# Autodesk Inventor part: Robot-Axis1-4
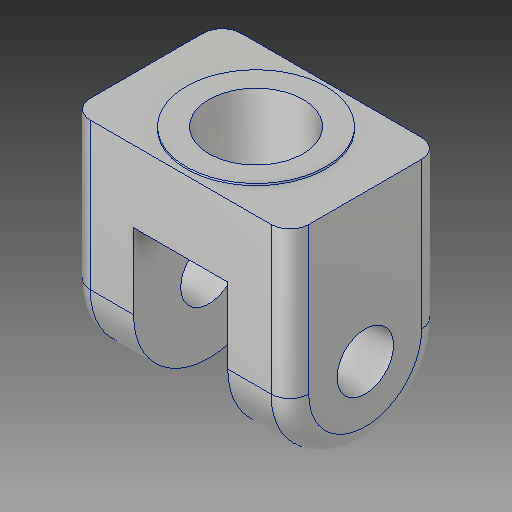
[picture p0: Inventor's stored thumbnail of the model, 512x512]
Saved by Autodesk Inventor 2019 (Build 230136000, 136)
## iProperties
Created: 2018-07
Part Number: Robot-Axis1-4
Material: Aluminum 6061
Description: 123456
Document SubType Name: Modeling
Designer: Power User
Mass: 1617.3 g
Surface Area: 678.793 cm^2
Volume: 599 cm^3
Density: 2.7 g/cm^3
Appearance: Aluminum - Flat
Title: GEAR
Author: Power User
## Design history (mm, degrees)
sketch "Sketch6" dims "d45" = 80
  geometry: L1 (0, 40)-(78, 40); L2 (78, 40)-(78, -40); L3 (78, -40)-(0, -40); L4 (0, -40)-(0, 40); 3 further points
  constraints: 8 end point, 3 horizontal, 2 parallel, 1 coincident, 1 midpoint, 1 perpendicular, 1 vertical alignment, 2 other
  dimensions: "d46" = 78 distance of L2.end L3.end
extrude "Extrusion5" new body sketch "Sketch6" stored distance "d47" = 116; taper "d48" = 0 deg
sketch "Sketch7"
  geometry: A1 r 40 centre (0, 0) between (-40, 0) and (40, 0) reference; 2 further points
  constraints: 1 coincident
hole "Hole2" sketch "Sketch7" at (0, 0) diameter "d49" = 30; stored, may be unused: countersink angle "d53" = 90 deg, drill point angle "d55" = 118 deg; dims "d50" = 6, "d51" = 4, "d52" = 2, "d54" = 8
sketch "Sketch8"
  geometry: L1 (-25, 40)-(25, 40); L2 (25, 40)-(25, -45.089); L3 (25, -45.089)-(-25, -45.089); L4 (-25, -45.089)-(-25, 40); L5 (58, 15)-(-58, 15) reference; L6 (-58, 15)-(-58, 78) reference; L7 (-58, 78)-(58, 78) reference; L8 (58, 78)-(58, 15) reference; L9 (-58, -15)-(58, -15) reference; L10 (58, -15)-(58, -40) reference; L11 (58, -40)-(-58, -40) reference; L12 (-58, -40)-(-58, -15) reference; 2 further points
  constraints: 8 end point, 2 parallel, 1 horizontal, 1 midpoint, 1 perpendicular, 1 vertical alignment
  dimensions: "d56" = 50 distance of L2.end L3.end; "d57" = 80 distance between parallel lines of L11 L1
extrude "Extrusion6" cut sketch "Sketch8" extent not by distance; stored distance "d58" = 116; taper "d59" = 0 deg
sketch "Sketch9"
  geometry: C1 r 37 at (58, 40); 1 further point
  constraints: 1 centre point, 1 coincident
  dimensions: "d64" = 74 diameter of C1
extrude "Extrusion7" join sketch "Sketch9" distance "d62" = 1; taper "d63" = 0 deg
sketch "Sketch10"
  geometry: C1 r 37 at (0, 0) reference; 2 further points
  constraints: 1 coincident
hole "Hole3" sketch "Sketch10" at (0, 0) diameter "d65" = 50; stored, may be unused: countersink angle "d69" = 90 deg, drill point angle "d71" = 118 deg; dims "d66" = 6, "d67" = 4, "d68" = 2, "d70" = 8
fillet "Fillet2" dims "d72" = 10
body "Solid2"
node "Project Cut Edges2"
